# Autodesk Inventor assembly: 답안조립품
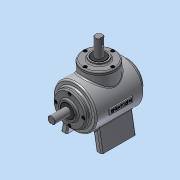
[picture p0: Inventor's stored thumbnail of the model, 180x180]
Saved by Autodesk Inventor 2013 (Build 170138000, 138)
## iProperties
Created: 2015-01
Part Number: 답안조립품
Document SubType Name: Assembly
Designer: dgall
Author: dgall
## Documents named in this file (15)
- C:\Users\dgall\Desktop\450105V1035\답안조립품.iam
- C:\Users\dgall\Desktop\450105V1035\1.본체.ipt
- C:\Users\dgall\Desktop\450105V1035\메인 베벨기어.ipt
- C:\Users\dgall\Desktop\450105V1035\메인 축.ipt
- 메인 축.ipt
- C:\Users\dgall\Desktop\450105V1035\서브 베벨기어.ipt
- C:\Users\dgall\Desktop\450105V1035\서브 축.ipt
- 서브 축.ipt
- C:\Users\dgall\Desktop\450105V1035\베어링 6203.ipt
- C:\Users\dgall\Desktop\450105V1035\키 4x4.ipt
- C:\Users\dgall\Desktop\450105V1035\키 5x5.ipt
- C:\Users\dgall\Desktop\450105V1035\커버2.ipt
- C:\Users\dgall\Desktop\450105V1035\커버.ipt
- C:\Users\dgall\Desktop\450105V1035\오일실.ipt
- C:\Users\dgall\Desktop\450105V1035\M4.ipt
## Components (13 placed, 2 different names)
1. 1.본체:1
2. M4:3
3. M4:4
4. M4:5
5. M4:6
6. M4:1
7. M4:7
8. M4:8
9. M4:9
10. M4:2
11. M4:10
12. M4:11
13. M4:12
